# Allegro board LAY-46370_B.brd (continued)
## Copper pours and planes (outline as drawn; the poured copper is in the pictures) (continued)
GND on BOTTOM: 86.92,138.75 89.8,138.75 90.17,138.38 90.17,136.22 89.84,135.89 88.58,135.89 87.99,135.3 87.49,135.3 86.44,136.35 86.44,138.27
GND on BOTTOM: 166.38,97.21 172.94,97.21 173.46,96.68 173.46,93.23 172.97,92.73 166.58,92.73 166.06,93.25 166.06,96.88
GND on BOTTOM: 51.33,125.31 59.26,125.31 61.42,123.15 63.64,123.15 65.8,125.31 83.02,125.31 84.72,123.61 86.61,123.61 88.29,125.29 105.51,125.29 105.71,125.09 105.71,123.78 100.19,118.27 76.92,118.27 74.91,116.26 58.45,116.26 51,123.72 51,124.98
GND on BOTTOM: 115.79,80.51 121.16,80.51 121.55,80.13 121.55,75.5 120.42,74.37 114.96,74.37 114.33,75 114.33,79.05
GND on BOTTOM: 180.11,133.19 183.87,133.19 184.24,132.82 184.24,130.97 183.68,130.41 180.29,130.41 179.79,130.91 179.79,132.87
GND on BOTTOM: 141.15,84.63 140.99,84.47 139.17,84.47 138.97,84.67 138.97,91.89 139.33,92.25 140.83,92.25 141.15,91.93
GND on BOTTOM: 19.52,42.66 62.79,42.66 63.22,42.23 63.22,40.35 62.95,40.07 54.4,40.07 52.43,38.1 20.16,38.1 19.29,38.97 19.29,42.44
GND on BOTTOM: outline of 200 points within 0.51,0.51 209.49,151.89
GND on BOTTOM: 63.77,138.23 67.42,138.23 67.78,137.87 67.78,135.73 67.23,135.18 65.69,135.18 65.6,135.28 65.6,135.53 65.12,136.01 63.68,136.01 63.3,136.38 63.3,137.76
GND on BOTTOM: 102.1,138.34 106.1,138.34 107.3,137.14 107.3,135.32 106.68,135.32 106.59,135.41 106.59,135.69 106.2,136.08 102.95,136.08 102.52,135.65 102.52,135.3 102.4,135.18 101.84,135.18 101.66,135.36 101.66,137.9
GND on BOTTOM: 113.2,138.04 115.94,138.04 116.16,137.82 116.16,136.43 115.76,136.02 113.84,136.02 113.46,135.65 113.46,135.26 113.42,135.21 112.12,135.21 111.73,135.61 111.73,136.57
GND on BOTTOM: 126.36,138.42 130.37,138.42 131.57,137.22 131.57,135.41 130.95,135.41 130.86,135.5 130.86,135.77 130.47,136.17 127.22,136.17 126.79,135.74 126.79,135.39 126.67,135.27 126.1,135.27 125.93,135.45 125.93,137.99
GND on BOTTOM: outline of 146 points within 18.38,42.01 143.13,118.66 ; 1 cut-out
GND on BOTTOM: 30.96,140.67 59.01,140.67 59.59,140.08 59.59,136.44 59.21,136.06 58.23,136.06 57.88,135.71 57.88,135.24 57.82,135.17 57.27,135.17 57.15,135.29 57.15,135.59 56.75,135.99 55.1,135.99 54.76,135.65 54.76,135.24 54.67,135.15 44.14,135.15 43.91,135.38 41.47,135.38 40.77,136.08 34.08,136.08 33.77,135.77 33.77,135.27 33.73,135.24 33.17,135.24 32.93,135.47 32.93,135.84 32.67,136.1 31.33,136.1 30.62,135.38 29.89,135.38 29.42,135.85 29.42,139.13
GND on BOTTOM: 78.18,138.34 82.18,138.34 83.38,137.14 83.38,135.32 83.2,135.14 82.63,135.14 82.11,135.66 79.09,135.66 78.61,135.18 77.92,135.18 77.74,135.36 77.74,137.9
GND on BOTTOM: 101,30.08 105.79,30.08 106.03,29.84 106.03,28.35 105.53,27.85 104,27.85 103.63,27.48 103.63,26.87 103.68,26.82 103.47,26.61 100.41,26.61 100.09,26.29 99.67,26.29 99.56,26.4 99.56,29.15 100.05,29.63 100.55,29.63
GND on BOTTOM: 167.99,84.66 164.37,84.66 164.13,84.91 164.13,86.45 164.39,86.71 166.06,86.71 166.31,86.46 166.31,85.96 166.49,85.78 167.96,85.78 168.17,85.57 168.17,84.84
GND on BOTTOM: 145.66,130.19 147.58,128.27 147.58,125.79 148.15,125.22 158.26,125.22 158.96,125.92 173.6,125.92 174.56,124.96 174.56,119.25 173.78,118.46 110.18,118.46 109.26,119.38 109.26,122.17 112.36,125.26 125.3,125.26 127.05,123.52 133.98,123.52 135.5,125.05 135.5,125.79 134.2,127.09 92,127.09 92,127.1 87.86,127.1 87.12,127.84 87.12,129.52 87.79,130.19
GND on L2_GND1, L7_GND2: 0.51,147.32 1.85,150.55 5.08,151.89 204.92,151.89 208.15,150.55 209.49,147.32 209.49,5.08 208.15,1.85 204.92,0.51 198.28,0.51 198.28,1.56 198.07,1.77 191.92,1.77 191.68,1.52 191.68,0.51 187.43,0.51 187.43,11.22 186.31,12.33 181.11,12.33 176.22,7.44 164.3,7.44 159.31,12.43 139.73,12.43 138.9,11.61 138.9,9.06 137.19,7.35 126.42,7.35 121.6,12.17 73.47,12.17 71.81,10.51 71.81,0.51 5.08,0.51 1.85,1.85 0.51,5.08
GND on L3_IN1: 110.22,120.56 115.5,120.56 118.76,123.83 123.08,123.83 123.56,123.35 123.56,111.36 117.01,104.81 108.66,104.81 107.87,105.6 107.87,109.57 111.7,113.41 111.7,116.85 109.83,118.73 109.83,120.17
GND on L3_IN1: 59.39,101.42 103.68,101.42 104.99,100.11 122.42,100.11 141.91,119.6 141.91,126.75 142.83,127.66 165.23,127.66 168.72,124.18 169.85,124.18 170.33,123.7 170.33,97.5 169.81,96.97 169.81,92.66 167.98,90.83 128.01,90.83 126.96,89.78 126.96,68.45 125.96,67.45 63.72,67.45 57.39,73.78 57.39,99.42
GND on L3_IN1: 0.51,147.32 1.85,150.55 5.08,151.89 204.92,151.89 208.15,150.55 209.49,147.32 209.49,5.08 208.15,1.85 204.92,0.51 198.27,0.51 198.27,1.56 198.07,1.77 191.92,1.77 191.68,1.52 191.68,0.51 187.39,0.51 187.39,11.27 185.9,12.76 180.36,12.76 175.22,7.62 166.17,7.62 160.6,13.19 139.62,13.19 138.13,11.7 138.13,10.44 138.16,10.41 138.16,9.71 136.04,7.59 128.22,7.59 123.34,12.47 73.15,12.47 73.14,12.47 71.23,10.56 71.23,0.51 5.08,0.51 1.85,1.85 0.51,5.08 ; 3 cut-outs
GND on L6_IN2: 18.44,124.88 23.19,124.88 24.26,123.81 24.26,122.57 24.8,122.04 24.8,77.69 23.75,76.64 20.12,76.64 19.22,77.54 19.22,83.39 18.52,84.08 14.98,84.08 14.8,83.9 14.8,81.57 15.68,80.7 15.68,54.67 13.84,52.84 10.86,52.84 5.66,58.04 5.66,87.98 17.67,100 17.67,124.12
GND on L6_IN2: outline of 231 points within 0.51,0.51 209.49,151.89 ; 1 cut-out
GND on L6_IN2: 56.16,132.35 61.34,132.35 61.88,131.81 61.88,120.58 69.39,113.07 69.39,109.46 68.63,108.7 67.53,108.7 56.18,97.35 56.18,57.9 46.77,48.49 37.4,48.49 36.95,48.93 36.95,63.46 36.95,64.72 27.58,74.09 27.58,104.01 28.88,105.31 45.72,105.31 47.38,106.97 47.38,123.56
GND on L6_IN2: 109.04,84.4 120.07,84.4 122.54,81.93 122.54,49.65 121.42,48.53 119.71,48.53 118.82,49.43 118.82,54.49 115.99,57.32 115.99,75.48 112.18,79.29 109.31,79.29 108.33,80.27 108.33,83.68
GND on L6_IN2: 63.36,132.71 72.5,132.71 73.83,131.38 73.83,117.04 72.82,116.03 69.66,116.03 64.3,121.38 64.3,123.81 62.86,125.24 62.86,132.21
GND_CHASSIS on TOP: 111.32,16.43 117.66,16.43 118.26,15.83 118.26,13.86 118.23,13.84 119.85,12.22 121.51,12.22 126.37,7.36 137.32,7.36 139.03,9.07 139.03,10.49 140.57,12.03 158.95,12.03 164.05,6.93 176.58,6.93 181.41,11.76 184.99,11.76 185.86,10.89 185.86,0.51 108.71,0.51 108.71,0.53 73.27,0.53 73.27,11.29 73.55,11.56 109.88,11.56 110.86,12.54 110.86,15.97
GND_CHASSIS on BOTTOM: 112.12,11.63 121.3,11.63 126.06,6.87 137.52,6.87 139.55,8.9 139.55,11.44 140.03,11.92 159,11.92 163.99,6.93 176.49,6.93 181.38,11.82 184.99,11.82 185.85,10.96 185.85,0.51 111.66,0.51 73.27,0.51 73.27,11.34 73.54,11.62 112.12,11.62
GND_CHASSIS on L2_GND1: 139.94,11.92 159.1,11.92 164.09,6.93 176.43,6.93 181.32,11.83 185.03,11.83 185.85,11.01 185.85,0.51 73.26,0.51 73.26,11.25 73.68,11.66 121.39,11.66 126.21,6.84 137.4,6.84 139.41,8.85 139.41,11.39
GND_CHASSIS on L3_IN1: 139.8,11.77 159.17,11.77 164.1,6.85 176.41,6.85 181.32,11.75 184.93,11.75 185.86,10.82 185.86,0.51 73.28,0.51 73.28,11.29 73.67,11.69 121.36,11.69 126.22,6.83 137.38,6.83 139.4,8.85 139.4,11.38
GND_CHASSIS on L4_POWER_1: 139.94,11.92 159.1,11.92 164.09,6.93 176.43,6.93 181.32,11.83 184.99,11.83 185.87,10.94 185.87,0.51 73.29,0.51 73.29,11.28 73.68,11.66 121.39,11.66 126.21,6.84 137.4,6.84 139.41,8.85 139.41,11.39
GND_CHASSIS on L5_POWER_2: 139.94,11.92 159.1,11.92 164.09,6.93 176.43,6.93 181.32,11.83 185.07,11.83 185.89,11 185.89,0.51 73.26,0.51 73.26,11.25 73.68,11.66 121.39,11.66 126.21,6.84 137.4,6.84 139.41,8.85 139.41,11.39
GND_CHASSIS on L6_IN2: 139.96,11.91 159.11,11.91 164.1,6.93 176.45,6.93 181.36,11.83 185.01,11.83 185.89,10.96 185.89,0.51 73.31,0.51 73.31,11.27 73.71,11.68 121.37,11.68 126.23,6.82 137.38,6.82 139.42,8.86 139.42,11.38
GND_CHASSIS on L7_GND2: 139.94,11.92 159.1,11.92 164.09,6.93 176.43,6.93 181.32,11.83 184.97,11.83 185.88,10.91 185.88,0.51 73.27,0.51 73.27,11.26 73.68,11.66 121.39,11.66 126.21,6.84 137.4,6.84 139.41,8.85 139.41,11.39
VBUS_DBG on TOP: 9.14,7.52 12.69,7.52 12.91,7.31 12.91,5.9 12.05,5.04 12.05,3.72 11.95,3.63 11.24,3.63 10.8,4.06 10.8,5.78 10.57,6.01 9.35,6.01 8.92,6.43 8.92,7.3
VBUS_IN on TOP: 28.49,32.08 32.8,32.08 33.21,31.66 33.21,29.67 30.27,26.73 30.27,25.67 30.13,25.53 28.5,25.53 28.24,25.8 28.24,31.82
VBUS_IN on BOTTOM: 20.19,36.98 46.02,36.98 49.95,33.05 49.95,29.3 49.52,28.87 47.5,28.87 45.68,30.69 28.38,30.69 27.39,31.68 21.31,31.68 20.06,32.92 20.06,36.86
VBUS_IN on BOTTOM: 22.63,99.23 23.12,99.23 23.21,99.14 23.21,97.78 25.38,95.61 25.38,91.67 25.17,91.46 20.48,91.46 20,91.95 20,95.83 20.93,96.77 21.73,96.77 22.55,97.58 22.55,99.15
VBUS_IN on BOTTOM: 36.34,73.32 45.8,73.32 46.09,73.03 46.09,69.6 45.09,68.6 43.6,68.6 42.6,67.6 42.6,64.65 42.45,64.5 42.31,64.5 42.1,64.72 42.1,67.39 39.32,70.16 36.39,70.16 36.14,70.42 36.14,73.11
VBUS_IN on L3_IN1: 44.53,36.43 37.7,29.6 29.71,29.6 28.8,30.51 28.8,33.96 32.11,37.27 32.11,59.17 36.72,63.78 36.72,72.78 35.63,73.87 24.39,73.87 24.35,73.83 20.51,73.83 19.75,74.59 19.75,95.68 19.77,95.7 19.77,98.68 21.16,100.07 43,100.07 44.53,98.54
VBUS_USB_DBG on TOP: 28.87,60.76 28.87,59.95 29.33,59.49 29.33,58.57 29.21,58.45 27.92,58.45 27.8,58.57 27.8,60.76
VBUS_USB_DBG on TOP: 2.36,12.37 3.08,12.37 3.24,12.22 3.24,11.13 3.52,10.85 4.21,10.85 4.49,11.12 4.49,12.28 4.55,12.34 5.45,12.34 5.74,12.05 5.74,10.01 6.46,9.29 9.5,9.29 9.79,9 9.79,8.02 9.5,7.73 7.01,7.73 6.12,8.63 3.17,8.63 2.2,9.59 2.2,12.22
VBUS_USB_DBG on L3_IN1: 30.96,36.89 28.18,34.11 28.18,13.53 22.6,7.95 2.99,7.95 1.83,9.11 1.83,12.38 1.88,12.44 1.88,13.7 3.8,15.62 16.83,15.62 18.02,16.82 18.02,53.19 25.24,60.4 30.38,60.4 30.96,59.82
VCC_FT_1V8 on L3_IN1: 12.53,72.94 35.77,72.94 36.37,72.34 36.37,64.28 33.9,61.81 25.8,61.81 17.36,53.36 17.36,18.09 15.52,16.26 5.56,16.26 3.84,17.98 3.84,64.24
VCC_FT_3V3 on L4_POWER_1: 0.51,75.5 23.66,75.5 26.43,72.73 26.43,22.21 22.35,18.12 22.35,0.51 5.08,0.51 1.85,1.85 0.51,5.08
VDD_1V8 on TOP: 94.54,60.63 96.7,60.63 96.81,60.53 96.81,59 97.09,58.72 97.09,57.66 96.99,57.56 94.89,57.56 94.52,57.92 94.52,60.62
VDD_1V8 on BOTTOM: 94.68,59.78 96.26,59.78 97.17,58.86 97.17,57.78 97.11,57.72 96.72,57.72 95.98,56.98 93.78,56.98 93.57,57.19 93.57,58.67
VDD_1V8 on BOTTOM: 90.35,135.33 90.35,133.77 89.85,133.27 87.22,133.27 86.95,133.55 86.95,134.35 87.61,135.01 88.24,135.01 88.38,135.15 88.38,135.25 88.46,135.33 88.5,135.33 88.62,135.45 90.23,135.45
VDD_1V8 on BOTTOM: 114.02,135.7 114.98,135.7 115.19,135.49 115.19,133.67 114.69,133.17 112.07,133.17 111.8,133.44 111.8,134.25 112.46,134.91 113.62,134.91 113.94,135.22 113.94,135.61
VDD_1V8 on BOTTOM: 39.73,135.74 40.84,135.74 41.02,135.56 41.02,135.26 41.2,135.08 42.37,135.08 42.6,134.86 42.6,133.32 42,132.73 40.1,132.73 39.53,133.3 39.53,135.54
VDD_1V8 on BOTTOM: 63.95,135.68 65.06,135.68 65.15,135.59 65.15,135.18 65.45,134.88 66.51,134.88 66.81,134.58 66.81,133.27 66.22,132.67 64.32,132.67 63.75,133.24 63.75,135.48
VDD_1V8 on BOTTOM: 138.01,135.56 138.96,135.56 139.17,135.35 139.17,133.53 138.68,133.03 136.05,133.03 135.78,133.31 135.78,134.11 136.44,134.77 137.61,134.77 137.92,135.09 137.92,135.47
VDD_1V8 on L5_POWER_2: 0.51,147.32 1.85,150.55 5.08,151.89 204.92,151.89 208.15,150.55 209.49,147.32 209.49,5.08 208.15,1.85 204.92,0.51 198.28,0.51 198.28,1.56 198.07,1.77 191.92,1.77 191.68,1.52 191.68,0.51 187.43,0.51 187.43,11.22 186.31,12.33 181.11,12.33 176.22,7.44 164.3,7.44 159.31,12.43 139.73,12.43 138.9,11.61 138.9,9.06 137.19,7.35 126.42,7.35 121.6,12.17 73.47,12.17 71.81,10.51 71.81,0.51 5.08,0.51 1.85,1.85 0.51,5.08
VDD_3V3 on TOP: 94.67,66.26 96.53,66.26 96.78,66.01 96.78,63.05 96.72,62.99 94.57,62.99 94.49,63.07 94.49,66.08
VDD_3V3 on BOTTOM: 92.8,66.32 96.5,66.32 96.77,66.05 96.77,64.12 96.16,63.51 94.78,63.51 92.77,65.52 92.77,66.29
VDD_3V3 on L4_POWER_1: 0.51,147.32 1.85,150.55 5.08,151.89 204.92,151.89 208.15,150.55 209.49,147.32 209.49,5.08 208.15,1.85 204.92,0.51 198.28,0.51 198.28,1.56 198.07,1.77 191.92,1.77 191.68,1.52 191.68,0.51 187.43,0.51 187.43,11.22 186.31,12.33 181.11,12.33 176.22,7.44 164.3,7.44 159.31,12.43 139.73,12.43 138.9,11.61 138.9,9.06 137.19,7.35 126.42,7.35 121.6,12.17 73.47,12.17 71.81,10.51 71.81,0.51 22.85,0.51 22.85,17.91 26.94,22 26.94,72.94 23.87,76.01 0.51,76.01
VDD_5V on TOP: 200.77,104.14 200.66,104.03 199.75,104.03 199.62,104.17 199.62,105.08 198.99,105.71 195.35,105.71 195.32,105.74 187.43,105.74 187.21,105.96 187.21,112.37 187.55,112.71 195.1,112.71 198.12,109.69 199.99,109.69 200.77,108.91
VDD_5V on TOP: 67.94,40.26 68.5,40.26 68.67,40.09 68.67,37.78 68.38,37.49 66.81,37.49 66.59,37.71 66.59,39.16 67.06,39.62 67.64,39.62 67.82,39.81 67.82,40.14
VDD_5V on TOP: 176.21,127.05 182.14,127.05 182.23,126.96 182.23,126.29 182.02,126.07 176.84,126.07 176.56,125.79 176.56,123.85 176.39,123.68 175.55,123.68 175.44,123.8 175.44,126.28
VDD_5V on BOTTOM: 31.21,135.53 32.63,135.53 32.72,135.44 32.72,133.45 32.29,133.02 30.23,133.02 29.75,133.5 29.75,134.8 29.99,135.05 30.79,135.05 31.19,135.45 31.19,135.52
VDD_5V on BOTTOM: 102.91,135.62 104.29,135.62 104.45,135.45 104.45,133.64 104.1,133.29 101.9,133.29 101.47,133.72 101.47,134.69 101.8,135.02 102.61,135.02 102.86,135.28 102.86,135.58
VDD_5V on BOTTOM: 127.14,135.61 128.52,135.61 128.69,135.45 128.69,133.63 128.33,133.28 126.13,133.28 125.7,133.71 125.7,134.68 126.04,135.01 126.84,135.01 127.09,135.27 127.09,135.57
VDD_5V on BOTTOM: 55.26,135.42 56.64,135.42 56.81,135.25 56.81,133.44 56.46,133.09 54.26,133.09 53.83,133.52 53.83,134.49 54.16,134.82 54.96,134.82 55.22,135.08 55.22,135.38
VDD_5V on BOTTOM: 55.33,105.32 61.58,105.32 61.83,105.07 61.83,101.76 60.94,100.87 57.07,100.87 56.49,101.45 56.49,102.16 56.36,102.29 55.15,102.29 55.07,102.37 55.07,105.06
VDD_5V on BOTTOM: 79.18,135.42 80.56,135.42 80.73,135.25 80.73,133.44 80.37,133.09 78.17,133.09 77.74,133.52 77.74,134.49 78.08,134.82 78.88,134.82 79.13,135.08 79.13,135.38
VDD_5V on L3_IN1: 57.38,102.33 56.12,101.07 22.56,101.07 20.77,102.86 20.77,140.32 24.29,143.84 136.07,143.84 140.22,147.99 189.27,147.99 200.43,136.83 200.43,34.14 185.78,19.5 178.1,19.5 169.51,28.09 111.73,28.09 110.61,29.21 110.61,36.7 107.6,39.7 76.54,39.7 73.9,37.06 66.68,37.06 66.19,37.56 66.19,39.6 76.6,50.01 188.7,50.01 191.41,52.73 191.41,105.34 189.41,107.35 182.02,107.35 181.14,108.22 181.14,135.95 178.68,138.41 169.4,138.41 159.26,128.27 31.84,128.27 30.32,126.75 30.32,122.3 34.42,118.2 47.36,118.2 57.38,108.18
AUD_5V on L6_IN2: 187.31,30.14 189.69,30.14 190,29.82 190,28.27 190.38,27.9 191.09,27.9 191.3,27.68 191.3,22.45 189.94,21.09 187.31,21.09 186.78,21.62 186.78,29.61
DCDC_5V on TOP: 174.43,137.66 174.76,137.66 175.04,137.37 175.04,134.36 174.62,133.94 173.09,133.94 172.13,134.9 172.13,136.7 171.42,137.4 171.42,138.76 171.56,138.89 173.92,138.89 174.11,138.7 174.11,137.98
DCDC_5V on TOP: 59.55,37.08 62.45,37.08 62.64,36.9 62.64,36.05 62.52,35.92 60.45,35.92 59.9,35.37 59.9,33.94 59.79,33.83 59.29,33.83 59.2,33.92 59.2,35.06 59.21,35.07 59.21,36.81 59.4,37 59.47,37
DCDC_5V on TOP: 58,22.61 58.35,22.61 58.47,22.49 58.47,21.29 58.41,21.23 58.41,20.79 58.14,20.52 57.06,20.52 56.17,19.64 54.96,19.64 54.69,19.92 54.69,22.83 55,23.15 57.47,23.15
DCDC_5V on TOP: 25.51,60.8 27.58,60.8 27.68,60.7 27.68,59.16 27.51,59 24.99,59 24.64,59.34 24.64,60.72 24.7,60.78 25.49,60.78
DCDC_5V on BOTTOM: 77.65,63.67 85.23,63.67 85.46,63.44 85.46,59.05 81.39,54.98 81.39,51.73 81.03,51.38 76.72,51.38 75.9,52.2 75.9,61.92
DCDC_5V on BOTTOM: 41.5,106.9 41.72,106.9 41.87,106.76 41.87,104.87 43.25,103.49 45.96,103.49 46.23,103.21 46.52,103.21 46.52,103.22 48.12,103.22 51.13,100.21 55.88,100.21 56.52,99.56 57.88,99.56 58.06,99.74 58.06,100.37 59.93,100.37 60.18,100.12 60.18,97.53 59.93,97.28 49.89,97.28 47.12,100.04 38.37,100.04 38.17,100.24 38.17,103.68 39.21,104.71 41.07,104.71 41.44,105.09 41.44,106.85
DCDC_5V on BOTTOM: 46.35,61.68 50.99,61.68 51.32,61.34 51.32,55.09 48.35,52.11 35.42,52.11 33.25,54.28 33.25,56.52 34.91,58.17 34.91,59.9 34.65,60.16 28.26,60.16 27.27,59.17 25.49,59.17 24.91,59.75 24.91,63.1 25.36,63.56 36.08,63.56 37.32,64.79 39.38,64.79 39.46,64.7 39.46,64.04 39.12,63.7 38.53,63.7 38.14,63.31 38.14,60.51 38.48,60.18 38.48,59.84 38.37,59.74 37.76,59.74 37.15,59.13 37.15,55.31 38.32,54.14 45.4,54.14 46.23,54.97 46.23,61.56
DCDC_5V on BOTTOM: 59.77,39.2 63.08,39.2 63.28,39 63.28,36.52 62.89,36.12 59.99,36.12 59.53,36.58 59.53,38.96
DCDC_5V on L3_IN1: 77.23,51.1 65.59,39.46 65.59,36.22 64.14,34.77 60.34,34.77 59.39,35.73 59.39,37.73 58.19,38.93 47.56,38.93 47.54,38.96 46.39,38.96 45.38,39.97 45.38,97.55 46.93,99.1 55.55,99.1 56.93,97.72 56.93,73.6 63.39,67.13 150.46,67.13 170.84,87.51 170.84,136.79 171.94,137.89 177.84,137.89 179.49,136.25 179.49,53.56 177.03,51.1
DCDC_5V on L6_IN2: 59.59,37.49 62.98,37.49 63.62,36.85 63.62,22.73 61.05,20.16 56.36,20.16 55.8,20.73 55.8,33.69
ETH1_AVDD1V0 on L3_IN1: 87.84,30.03 87.84,26.85 85.87,24.88 79.88,24.88 78.86,25.9 78.86,28.72 80.27,30.13 81.71,30.13 82.58,30.99 86.88,30.99
ETH1_DVDD3V3 on L3_IN1: 74.61,36.21 76.89,36.21 77.27,35.83 77.27,33.66 78.01,32.92 80.67,32.92 81.11,32.48 81.11,30.96 80.67,30.52 80.24,30.52 78.57,28.85 78.57,27.23 77.98,26.63 75.07,26.63 74.22,27.48 74.22,35.81
ETH1_VDDIO on L3_IN1: 78.29,38.58 88.07,38.58 90.18,36.46 90.18,36.41 91.65,34.93 91.65,27 90.67,26.01 89.09,26.01 88.47,26.63 88.47,30.88 88.48,30.9 87.88,31.5 81.55,31.5 81.32,31.74 81.32,32.73 80.7,33.35 78.25,33.35 77.78,33.81 77.78,38.07
ETH_AVDD1V0 on L3_IN1: 103.24,33.28 106.27,33.28 106.88,32.66 106.88,28.12 103.75,24.99 99.16,24.99 97.69,26.45 97.69,28.54 98.94,29.79 102.78,29.79 102.98,29.99 102.98,33.01
ETH_DVDD3V3 on L3_IN1: 92.91,35.97 98.65,35.97 100.1,34.52 100.1,31.19 96.65,27.74 93.03,27.74 92.37,28.41 92.37,35.43
ETH_VDDIO on L3_IN1: 102.59,37.44 106.19,37.44 106.23,37.4 106.86,37.4 106.9,37.36 108.67,37.36 110.21,35.82 110.21,27.74 109.79,27.32 108.18,27.32 107.54,27.95 107.54,32.67 106.42,33.79 103.06,33.79 102.59,33.32 102.59,32.22 101.85,31.48 100.69,31.48 100.41,31.76 100.41,35.26
FAN_5V on TOP: 168.22,120.9 173.69,120.9 175.63,122.83 177.06,122.83 177.18,122.71 177.18,119.25 176.53,118.59 168.33,118.59 168.06,118.86 168.06,120.73
PER_12V on BOTTOM: 32.06,104.06 31.39,103.39 28.31,103.39 27.61,104.08 27.61,112.3 26.18,113.73 18.41,113.73 17.84,114.3 17.84,118.45 17.92,118.53 17.92,121.52 23.52,127.12 23.52,143.88 28.23,148.59 101.14,148.59 108.78,140.96 135.44,140.96 135.65,140.74 135.65,135.73 134.71,134.79 134.71,133.46 134.47,133.21 133.66,133.21 133.25,133.61 133.25,136.66 131.1,138.81 113.73,138.81 110.86,135.94 110.86,133.65 110.42,133.21 109.59,133.21 109.03,133.77 109.03,136.55 104.21,141.38 31.02,141.38 28.52,138.88 28.52,124.3 32.06,120.76
USB1_OTG_VBUS on TOP: 38.56,11.98 40.31,11.98 40.65,11.64 40.65,9.62 40.38,9.35 38.78,9.35 38.46,9.66 38.46,11.89
USB1_OTG_VBUS on L6_IN2: 38.82,11.88 43.93,11.88 46.72,9.08 50.39,9.08 51.07,8.4 51.07,4.91 50.12,3.95 39.03,3.95 38.49,4.49 38.49,11.55
USB1_OTG_VBUS_F on TOP: 36.03,14.56 38.75,14.56 38.87,14.44 38.87,12.87 37.67,11.67 37.67,10.08 37.38,9.79 36.1,9.79 35.89,10.01 35.89,14.41
USB1_OTG_VBUS_F on TOP: 59.09,35.04 59.06,35.01 59.06,33.88 59.24,33.7 59.82,33.7 59.88,33.64 59.88,33.46 59.83,33.41 58.48,33.41 58.39,33.5 58.39,35.25 57.51,36.13 56.7,36.13 56.69,36.14 56.19,36.14 56.04,36.29 56.04,37.14 56.16,37.27 58.94,37.27 59.09,37.12
USB1_OTG_VBUS_F on TOP: 70.18,36.01 72.05,36.01 72.09,35.97 72.61,35.97 72.7,35.88 72.7,33.77 72.12,33.19 71.63,33.19 71.62,33.2 70.5,33.2 70.27,32.97 68.97,32.97 68.89,33.05 68.89,33.39 69.02,33.51 69.58,33.51 69.97,33.9 69.97,35.81
USB1_OTG_VBUS_F on BOTTOM: 56.06,39.24 59.03,39.24 59.15,39.11 59.15,36.91 58.92,36.68 56.24,36.68 55.87,37.06 55.87,39.05
USB1_OTG_VBUS_F on L3_IN1: 58.37,37.98 59,37.34 59,34.23 60.04,33.19 70.09,33.19 70.8,33.89 70.8,36.11 71.08,36.39 72.91,36.39 73.23,36.08 73.23,27.68 71.55,26.01 52.24,26.01 38.87,12.63 34.22,12.63 34.15,12.7 30.46,12.7 29.53,13.63 29.53,27.01 30.8,28.27 37.9,28.27 47.61,37.98
USB1_VBUS_IN on TOP: 54.6,36.02 57.43,36.02 58.24,35.22 58.24,33.51 58.15,33.42 54.83,33.42 54.48,33.78 54.48,35.9
USB1_VBUS_IN on BOTTOM: 50.62,37.43 54.5,37.43 55.99,35.94 55.99,31.81 53.23,29.06 51.13,29.06 50.97,29.22 50.97,32.76 50.37,33.35 50.37,37.18
USB2_HOST_VBUS on TOP: 62.01,17.68 60.05,17.68 59.71,18.02 59.71,22.22 59.56,22.37 59.28,22.37 59.17,22.47 59.17,22.56 59.24,22.62 60.42,22.62 60.42,22.62 63.88,22.62 64.18,22.32 64.18,19.85
USB2_HOST_VBUS on L3_IN1: 63.37,18.51 64.96,16.91 64.96,12.4 64.19,11.63 58.91,11.63 56.74,13.8 56.74,16.45 58.8,18.51
USB_PWR_VBUS_F on TOP: 31.24,27.38 34.34,27.38 34.84,26.87 34.84,23.16 34.61,22.92 31.73,22.92 31.42,23.24 31.42,24.47 30.9,24.98 29.03,24.98 28.94,25.08 28.94,25.25 29.04,25.35 30.2,25.35 30.44,25.59 30.44,26.58
USB_PWR_VBUS_F on TOP: 33.23,14.63 35.48,14.63 35.56,14.54 35.56,10.2 35.13,9.77 33.63,9.77 32.82,10.58 32.82,12.82 32.33,13.31 32.33,15.11 31.92,15.52 31.92,15.83 31.99,15.9 32.4,15.9 32.79,15.51 32.79,15.06
USB_PWR_VBUS_F on BOTTOM: 32.62,15.66 34.23,15.66 34.59,15.3 34.59,13.47 34.37,13.26 32.77,13.26 32.58,13.45 32.58,15.62
USB_PWR_VBUS_F on L6_IN2: 32.58,23.63 34.51,23.63 34.88,23.26 34.88,13.61 34.45,13.18 33.01,13.18 31.26,14.93 31.26,22.31
VEXP_3V3 on TOP: 186.47,105.04 191.91,105.04 192.5,104.44 192.5,102.83 191.12,101.45 188.7,101.45 188.13,100.88 186.93,100.88 186.42,101.39 186.42,104.98
VEXP_3V3 on L3_IN1: 190.07,55.26 185.99,51.18 182.75,51.18 181.7,52.24 181.7,105.29 182.62,106.21 188.77,106.21 190.07,104.91
VEXP_5V on TOP: 194.12,105.31 198.9,105.31 199.28,104.93 199.28,99.64 199.06,99.42 194.77,99.42 194.31,99.88 194.31,101.04 193.53,101.82 193.53,104.71
VEXT_3V3 on TOP: 184.07,112.83 185.73,112.83 186.1,112.46 186.1,103.09 185.97,102.95 184.22,102.95 183.88,103.29 183.88,112.64
VEXT_3V3 on BOTTOM: 58.26,135.72 59.34,135.72 59.44,135.61 59.44,133.32 59.24,133.11 57.67,133.11 57.26,133.52 57.26,134.85 57.28,134.86 57.9,134.86 57.91,134.86 58.18,135.12 58.18,135.63
VEXT_3V3 on BOTTOM: 82.27,135.12 82.5,134.89 83.49,134.89 83.59,134.79 83.59,133.36 83.33,133.1 81.39,133.1 81.21,133.28 81.21,135.3 82.04,135.3 82.22,135.12
VEXT_3V3 on BOTTOM: 105.11,135.74 106.01,135.74 106.11,135.65 106.11,135.27 106.34,135.04 107.34,135.04 107.43,134.94 107.43,133.51 107.17,133.25 105.23,133.25 105.05,133.43 105.05,135.69
VEXT_3V3 on BOTTOM: 129.36,135.81 130.27,135.81 130.37,135.71 130.37,135.34 130.6,135.1 131.59,135.1 131.69,135.01 131.69,133.58 131.43,133.32 129.49,133.32 129.31,133.5 129.31,135.75
VEXT_3V3 on BOTTOM: 126.53,77.41 126.45,77.33 122.78,77.33 122.49,77.62 122.49,80.79 123.13,81.43 128.55,81.43 128.65,81.34 128.65,81.01 128.43,80.79 126.77,80.79 126.53,80.55
VEXT_3V3 on BOTTOM: 34.26,135.76 35.36,135.76 35.64,135.48 35.64,133.26 35.36,132.98 33.66,132.98 33.14,133.49 33.14,134.86 33.23,134.95 33.85,134.95 34.07,135.17 34.07,135.57
VEXT_3V3 on BOTTOM: 39.98,114.64 42.51,114.64 43.32,113.83 43.32,112.1 42.8,111.58 42.8,109.22 41.83,108.25 41.83,107.19 41.8,107.16 41.53,107.16 41.46,107.23 41.46,108.37 40.6,109.24 40.6,111.25 39.88,111.96 39.88,114.54
VEXT_3V3 on L6_IN2: 30.73,146.73 173.92,146.73 196.73,123.92 196.73,106.84 195.92,106.03 189.51,106.03 186.34,102.86 183.95,102.86 182.05,104.76 156.91,104.76 154.66,107.02 154.66,115.4 141.23,128.82 131.31,128.82 127.14,124.65 127.14,78.03 126.48,77.37 123.94,77.37 123.23,78.09 123.23,128 118.16,133.07 56.57,133.07 47.07,123.56 47.07,107.37 45.87,106.17 30.73,106.17 29.11,107.79 29.11,145.11
VPCIE_3V3 on BOTTOM: 124.48,77.12 129.73,77.12 131.6,75.25 133.35,75.25 133.39,75.21 133.39,74.3 133.17,74.08 124.45,74.08 124.15,74.38 124.15,76.79
VPCIE_3V3 on BOTTOM: 168.27,86.17 166.82,86.17 166.61,86.39 166.61,86.72 166.33,87 164.43,87 162.79,88.64 162.79,90.65 163.22,91.08 172.77,91.08 173.1,90.74 173.1,89.6 169.66,86.16 168.27,86.16
VPCIE_3V3 on BOTTOM: 145.95,90.77 146.11,90.61 146.11,87.92 145.95,87.76 145.55,87.76 145.29,87.5 145.29,86.98 143.76,86.98 143.46,86.68 143.46,85.28 143.08,84.89 141.83,84.89 141.68,85.04 141.68,92.15 141.95,92.42 143.02,92.42 143.27,92.17 143.27,91.4 143.9,90.77
VPCIE_3V3 on L3_IN1: 129.15,90.21 168.94,90.21 169.18,89.96 169.18,86.41 150.47,67.7 128.39,67.7 127.8,68.29 127.8,88.86
VSD_3V3 on TOP: 179.75,135.49 181.97,135.49 182.55,134.91 182.55,131.84 182.54,131.83 182.54,130.78 182.01,130.24 178.51,130.24 178.09,130.66 178.09,133.83
VSD_3V3 on TOP: 96.97,64.78 97.83,64.78 97.94,64.68 97.94,63 97.91,62.97 96.97,62.97 96.92,63.02 96.92,64.73
VSD_3V3 on TOP: 135.67,99.07 137.28,99.07 137.61,98.74 137.61,97.32 137.3,97.01 135.58,97.01 135.38,97.21 135.38,98.78
VSD_3V3 on BOTTOM: 106.37,100.1 115.61,100.1 116.85,98.87 137.11,98.87 137.34,98.64 137.34,97.9 136.95,97.51 116.21,97.51 115.12,98.6 106.46,98.6 106.13,98.94 106.13,99.85
VSD_3V3 on BOTTOM: 180.61,138.54 181.41,138.54 181.62,138.33 181.62,136.22 182.99,134.85 183.49,134.85 183.87,134.47 183.87,133.6 183.76,133.48 179.98,133.48 179.5,133.97 179.5,134.71 180.56,135.77 180.56,138.49
VSD_3V3 on L6_IN2: 105.26,100.18 106.85,100.18 107.05,99.98 107.05,98.44 106.72,98.11 105.51,98.11 105.16,98.46 105.16,100.07
VSD_3V3 on L6_IN2: 97.13,65.33 98.82,65.33 98.97,65.19 98.97,63.08 98.67,62.78 97.23,62.78 96.94,63.07 96.94,65.14
VSYS_5V on TOP: 90.29,65.15 91.11,64.33 91.11,59.77 89.85,58.51 87.83,58.51 86.99,59.35 86.99,64.28 87.86,65.15
VSYS_5V on BOTTOM: 86.84,64.07 89.8,64.07 90.48,63.4 90.48,54.61 87.29,51.43 82.24,51.43 81.82,51.85 81.82,54.74 86.42,59.34 86.42,63.66
N103620792 on BOTTOM: 42.76,65.09 43.02,65.09 43.1,65.01 43.1,55.84 42.6,55.33 38.12,55.33 37.54,55.91 37.54,57.32 37.78,57.56 39.9,57.56 40.52,58.18 40.52,60.17 42.69,62.34 42.69,65.02
N107627023 on BOTTOM: 38.07,111.3 39.84,111.3 40.02,111.12 40.02,109.16 41.27,107.91 41.27,105.27 41.17,105.17 41.07,105.17 40.94,105.3 40.94,107.47 40.71,107.7 39.44,107.7 37.91,109.22 37.91,111.14
N108779922 on TOP: 58.67,22.61 58.93,22.61 59.06,22.48 59.06,22.26 59.13,22.19 59.32,22.19 59.53,21.99 59.53,18.5 59,17.97 57.21,17.97 56.94,18.24 56.94,19.96 57.19,20.21 58.26,20.21 58.61,20.56 58.61,22.56
N108973788 on TOP: 30.69,12.7 32.09,12.7 32.38,12.41 32.38,9.55 32.11,9.28 30.89,9.28 30.43,8.82 30.43,7.7 30.57,7.56 30.57,6.73 30.42,6.58 27.69,6.58 27.38,6.89 27.38,7.44 27.52,7.58 27.52,10.94 27.91,11.33 29.87,11.33 30.41,11.87 30.41,12.41
N108973788 on L6_IN2: 29.6,11.21 30.89,11.21 31.24,10.86 31.24,7.2 30.68,6.63 27.52,6.63 27.31,6.84 27.31,7.93 27.64,8.25 29.2,8.25 29.45,8.5 29.45,11.06
N109006844 on BOTTOM: 18.29,109.7 25.7,109.7 26.21,109.2 26.21,104.71 25.2,103.71 22.82,103.71 22.19,103.07 22.19,102.23 22.04,102.08 19.94,102.08 18.06,103.97 18.06,109.47
N110097895 on TOP: 38.68,21.19 41.6,21.19 41.72,21.06 41.72,20.48 41.58,20.35 40.11,20.35 39.42,19.66 39.42,16 38.99,15.57 34.6,15.57 34.32,15.85 34.32,17.1 34.63,17.41 37.45,17.41 38.1,18.06 38.1,19 38.63,19.53 38.63,21.13
N111151516 on BOTTOM: 126.91,80.59 128.93,80.59 132.05,77.46 132.69,77.46 132.95,77.2 132.95,75.91 132.85,75.81 131.53,75.81 129.99,77.35 126.87,77.35 126.74,77.48 126.74,80.42
N111155456 on BOTTOM: 133.89,75.27 137.43,75.27 137.74,74.96 137.74,74.17 137.51,73.94 134.08,73.94 133.75,74.27 133.75,75.14
N112068081 on BOTTOM: 24.65,56.76 28,56.76 28.4,56.36 28.4,54.38 24.8,54.38 24.51,54.67 24.51,56.61
N112246951 on TOP: 176.87,125.8 179.79,125.8 180.25,125.34 180.25,123.91 179.89,123.55 177.15,123.55 176.82,123.88 176.82,125.76
N112247388 on TOP: 178.09,122.86 179.49,122.86 179.69,122.66 179.69,119.44 179.39,119.14 179.01,119.14 178.85,119.3 178.85,120.54 177.98,121.41 177.98,122.74

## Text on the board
BOTTOM: LAY-46370 REV B
Ref Des/Silkscreen Bottom: EEPROM | EVENT_OUT | I2C5_SDA | EVENT_IN | SPDIF_RX | I2C5_SCL | SPDIF_TX | 1V8 | 3V3 | 5V | GND | + | - | 2230 | 2242 | 2260 | M.2 KEY-E | MicroSD | 700-46370 REV B | WIFI/BT ANTENNA
User.Comments: CR_SW_1 | CR_PS2_1
Ref Des/Silkscreen Top: 3V3 | VBUS2 | GND | CLKIN1 | CLKOUT1 | CLKIN2 | CLKOUT2 | DDC_SCL | VBUSIN1 | R | eARC | DDC_SDA | GPIO | MISO | 3.3V | SCLK | MOSI | SDA | SCL | 5V | RXD | TXD | CE0O | M7 TX | PWR | PER_12V | VBUSIN | 1V8 | MOD | PDM_3 | PDM_0 | PDM_1 | PDM_2 | DIS | 32K | RST | M2_3V3 | CLK_REQ | DIS2 | BT | PD | + | DN | DP | WLAN | - | I2C3_SDA | I2C3_SCL | I2C2_SDA | I2C2_SCL | PDM_CLK | SPK_LN | SPK_RN | SPK_LP | SPK_RP | RXD4 | RXD2 | TXD4 | TXD2 | M7  RX | A53 TX | A53 RX | SYS_NRST | SCLL | SDAL | SCLH | SDAH | CAN2_RX | CAN2_TX | CAN1_RX | CAN1_TX | UART_CTS | UART-RTS | UART_TXD | UART_RXD | DCDC_5V | EXT_3V3 | VDD_5V | BOOT MODE | Serial Download | Boot From Fuse | NAND 256Page | ECSPI Flash | NAND 512Page | eMMC/SDHC3 | MicroSD/SDHC2 | QSPI 3B Read | Infinite Loop | DEBUG | JTAG | PORT0 | 1000 SW4[1-4] | 0000 SW4[1-4] | 1110 SW4[1-4] | 0100 SW4[1-4] | 0110 SW4[1-4] | 0101 SW4[1-4] | 0001 SW4[1-4] | 0010 SW4[1-4] | 0011 SW4[1-4] | DSI MIPI | PORT1 | CSI1 MIPI | PORT2 | CSI2 MIPI | ENET1 | LVDS1 | ENET2 | CAN1 | LVDS0 | HDMI OUT | CAN2 | RESET | MicroSD | I2C_CN | EXP_CN | ONOFF | POWER | HEADPHONE | ON | OFF | BOOT SWITCH-SW4 | CPU BOARD | 8MPLUS-BB
FABRICATION_NOTES: 16 | 17 | 8 | 3.75 | 4.13 | 4.25 | 4.47 | 0.02
DIMENSION: GRID ORIGIN | PRIMARY DATUM | CANNOT ADD ANY PLANE ON EVERY LAYER ON THIS BOARD | VIEW FROM PRIMARY SIDE
User.11: ALL PARTS, MATERIALS AND FINISHED | ASSEMBLY SHALL NOT CONTAIN ANY OF | THE SUBSTANCES OF VERY HIGH CONCERN | (SVHC) ABOVE THE THRESHOLD VALUE PER | THE CURRENT ECHA LIST OF SVHC'S AND | WITH ANNEX XIV AND ANNEX XVII OF REACH | DIRECTIVE 76/769/EEC. A CERTIFICATE OF | COMPLIANCE IS REQUIRED UPON REQUEST. | ASSEMBLY SHALL MEET THE RoHS | COMMISSION DELEGATED DIRECTIVE (EU) | 2015/863 OF 31 MARCH  2015 AMENDING | ANNEX II TO DIRECTIVE 2011/65/EU. A | CERTIFICATE OF COMPLIANCE IS | REQUIRED UPON REQUEST. | [MM] | B | ADD SOME TEST PIN | 23/03/21 | 8MPLUS-BB | 1
User.12: Trace Width | Impedance | (Ohms) | (Mils) | Trace Spacing | "Airgap" | 3.50 | 4 | 5 | 4.5 | 90 | 3.6 | 3.3 | 6.9 | 7.2 | 100 | Single Ended | Differential
User.39: FIGURE | FINISHED_SIZE | 8.0 | 16.0 | 28.0 | 32.0 | 35.0 | 40.0 | 43.0 | 63.0 | 91.0 | 126.0 | 139.0 | 146.0 | 170.0 | 26.0 | 39.0 | 59.0 | 61.0 | 68.0 | 128.0 | 44.0x20.0 | 47.0x20.0 | 51.0x20.0 | 59.0x20.0 | 75.0x28.0 | 114.0x28.0 | DRILL CHART: TOP to BOTTOM | ALL UNITS ARE IN MILS | ROTATION | - | 90.000 | PLATED | NON-PLATED | QTY | 4573 | 24 | 25 | 30 | 22 | 15 | 18 | 4 | 2 | 5 | 3 | 1 | 10
User.41: 1 | 8 | 64 | 49 | 48 | 5 | 4 | 6 | 16 | 33 | 32 | 17 | 3 | B18 | A18 | 10 | A12 | B1 | A1 | B12 | 9 | 2 | 99 | 100 | 1V8 | M1 | M2 | C | A | 19 | 7 | 40 | 39 | 25 | 24 | 13 | 152.40 | 13.00 | 17.00 | 20.96 | 12.00 | 210.00 | 35.00 | 6.00 | 2019 NXP | MicroB | 5mm Round | USB | Cable | Type-C | 5MM Round | Type-A | HDMI | 6MM Round | Ethernet | DB9 | Audio Jack Cable | RCA | BOOT MODE | DEBUG | JTAG | PORT0 | GND | DSI MIPI | PORT1 | CSI1 MIPI | PORT2 | ONOFF | CSI2 MIPI | LVDS1 | LVDS0 | HDMI OUT | CAN2 | RESET | I2C_CN | POWER | ON | OFF | 8MPLUS-BB
